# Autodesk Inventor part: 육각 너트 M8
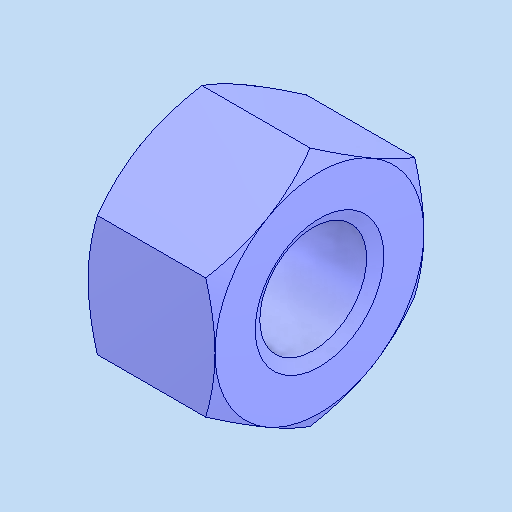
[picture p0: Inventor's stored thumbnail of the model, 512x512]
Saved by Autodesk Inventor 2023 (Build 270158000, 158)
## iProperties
Created: 2024-11
Part Number: 육각 너트 M8
Material: 강철, 연강
Description: 6각 너트 및 6각 가는 너트
Document SubType Name: Modeling
Designer: asung
Density: 7.85 g/cm^3
Appearance: 기본값
Author: jhkim
Sending System: Autodesk Inventor 2025
Preprocessor: ST-DEVELOPER v20
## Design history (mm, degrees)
node "육각 너트 M81"
node "솔리드1"
body "Solid1"
